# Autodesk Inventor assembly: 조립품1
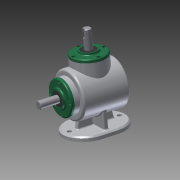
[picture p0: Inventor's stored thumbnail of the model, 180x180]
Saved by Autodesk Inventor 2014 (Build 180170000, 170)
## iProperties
Created: 2016-04
Part Number: 조립품1
Document SubType Name: Assembly
Designer: owner
Author: owner
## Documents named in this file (13)
- C:\Users\owner\Desktop\460407V1002\조립품1.iam
- C:\Users\owner\Desktop\460407V1002\답안.ipt
- C:\Users\owner\Desktop\460407V1002\커버.ipt
- C:\Users\owner\Desktop\460407V1002\베어링 6203.ipt
- C:\Users\owner\Desktop\460407V1002\메인 축.ipt
- 메인 축.ipt
- C:\Users\owner\Desktop\460407V1002\키 5x5.ipt
- C:\Users\owner\Desktop\460407V1002\메인 베벨기어.ipt
- C:\Users\owner\Desktop\460407V1002\서브 축.ipt
- 서브 축.ipt
- C:\Users\owner\Desktop\460407V1002\서브 베벨기어.ipt
- C:\Users\owner\Desktop\460407V1002\키 4x4.ipt
- C:\Users\owner\Desktop\460407V1002\오일실 17 32 8.ipt
